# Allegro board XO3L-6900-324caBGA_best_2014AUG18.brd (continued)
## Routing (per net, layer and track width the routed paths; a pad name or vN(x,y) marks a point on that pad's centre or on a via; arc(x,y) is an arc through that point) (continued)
PT35A: length 8.5
  TOP w0.102: BGA.A15 25.03,27.43 25.03,35.47
PT35B: length 8.5
  TOP w0.102: 25.21,35.47 25.21,27.43 BGA.A16
PT35C: length 12.5
  TOP w0.102: BGA.D14 v1(23.52,24.32)
  L3_SIGNAL w0.102: 24.75,35.47 24.75,25.68 24.59,25.52 24.14,25.52 23.92,25.29 BGA.D14 v1(23.52,24.32)
PT35D: length 11.8
  TOP w0.102: BGA.D15 v1(24.32,24.32)
  L3_SIGNAL w0.102: v1(24.32,24.32) 24.32,24.55 24.72,24.95 24.72,25.4 24.93,25.61 24.93,35.29
PT36A: length 9.3
  TOP w0.102: BGA.B16 25.92,26.72 25.92,35.47
PT36B: length 8.4
  TOP w0.102: 26.1,35.47 26.1,27.34 BGA.A17
PT36C: length 11.7
  TOP w0.102: BGA.C16 v1(25.12,25.12)
  L3_SIGNAL w0.102: v1(25.12,25.12) 25.49,25.49 26.19,25.49 26.45,25.75 35.96,25.75
PT36D: length 14.1
  TOP w0.102: BGA.E14 v1(23.52,23.52)
  L3_SIGNAL w0.102: v1(23.52,23.52) BGA.E14 24.49,23.92 24.72,24.15 24.72,24.5 24.94,24.72 25.29,24.72 25.88,25.31 26.26,25.31 26.53,25.58 35.96,25.58

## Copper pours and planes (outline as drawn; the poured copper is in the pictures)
GND on L2_GND: 1,1 1,39.64 39.64,39.64 39.64,1
VCC on L5_PWR: 21.59,5.41 21.59,18.02 21.25,18.35 18.35,18.35 18.35,19.05 19.18,19.05 19.18,20.38 18.41,21.15 18.41,21.53 21.29,21.53 21.59,21.83 21.59,35.21 34.51,35.21 34.51,21.59 22.67,21.59 20.76,19.68 20.76,19.37 20.94,19.19 22.64,19.19 25.57,16.26 34.5,16.26 34.5,5.41
VCCIO0 on L5_PWR: 18.41,21.65 18.41,22.29 19.11,22.29 19.11,24.89 5.66,24.89 5.66,35.21 21.46,35.21 21.46,21.91 21.21,21.65
VCCIO1 on L5_PWR: 20.89,19.41 20.89,19.62 22.73,21.46 34.51,21.46 34.51,16.38 25.65,16.38 22.73,19.3 21,19.3
VCCIO2 on L5_PWR: 18.35,18.22 21.21,18.22 21.46,17.97 21.46,5.41 5.63,5.41 5.63,16.26 16.38,16.26
VCCIO3 on L5_PWR: 5.64,16.39 5.64,19.81 17.97,19.81 18.22,19.56 18.22,18.29 16.32,16.39
VCCIO4 on L5_PWR: 5.64,19.94 5.64,21.46 18.29,21.46 18.29,21.08 19.05,20.32 19.05,19.18 18.35,19.18 18.35,19.62 18.03,19.94
VCCIO5 on L5_PWR: 5.66,21.59 5.66,24.76 18.99,24.76 18.99,22.42 18.29,22.42 18.29,21.59

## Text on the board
User.Comments: RP | RCI | 08/18/14 | DWG NO: | XO3L-69E-400caBGA | REVISION | 1.0 | SHEET | 1 | OF | XO3L-69E-400CABGA PCB BREAKOUT | LATTICE SEMICONDUCTOR CORPORATION
Ref Des/Silkscreen Top: PCB BREAKOUT | XO3L-69E-324CABGA | SEMICONDUCTOR | LATTICE | A | B | C | D | E | F | G | H | J | K | L | M | N | P | R | T | U | V | 1 | 2 | 3 | 4 | 5 | 6 | 7 | 8 | 9 | 10 | 11 | 12 | 13 | 14 | 15 | 16 | 17 | 18
PAGE_OUTLINE: 1 | INITIAL RELEASE | MM/DD/YYYY | XXXX XXXXX | SPECIAL INSTRUCTIONS: | 1/2 CU OZ FOR INTERNAL AND EXTERNAL LAYERS | MIN BOARD THICKNESS IS 62MILS. | DESIGNED BY: | APPROVED BY: | SIGNATURES         DATE | REV | DESCRIPTION | ESCAPE VIA DRILL | TRACE WIDTH/SPACE | ESCAPE VIA PAD | ARRAY SIZE | BGA LAND OPENING | BGA LAND PAD | PACKAGE SIZE | PITCH | SIGNAL         (L4) | SIGNAL         (L3) | GND     PLANE  (L2) | POWER   PLANE  (L5) | PRIMARY SIDE   (L1) | SECONDARY SIDE (L6) | SECONDARY SILKSCREEN | SECONDARY SOLDERMASK | PRIMARY SOLDERMASK | PRIMARY SILKSCREEN | 0.8 | 18 X 18 | 15 X 15 | 0.3048 | 0.3556 | 0.1524 | 0.10/0.08 | 0.4318 | MM | DATE | 708.66 X 708.66 | 590.55 X 590.55 | 31.5 | 4/3 | 17 | 12 | 6 | 14 | MILS | APPROVED | PCB BREAKOUT DETAILS | 6 LAYER STACKUP | REVISION
BODY_CENTER: FIGURE | SIZE | 10.0 | ALL UNITS ARE IN MILS | SIZE MM | 0.254 | PLATED | QTY | 83 | DRILL CHART: TOP to L4_SIGNAL
PLACE_BOUND_TOP: FIGURE | SIZE | 10.0 | ALL UNITS ARE IN MILS | SIZE MM | 0.254 | PLATED | QTY | 116 | DRILL CHART: TOP to L3_SIGNAL
DISPLAY_TOP: FIGURE | SIZE | 10.0 | ALL UNITS ARE IN MILS | SIZE MM | 0.254 | PLATED | QTY | 50 | DRILL CHART: TOP to BOTTOM
